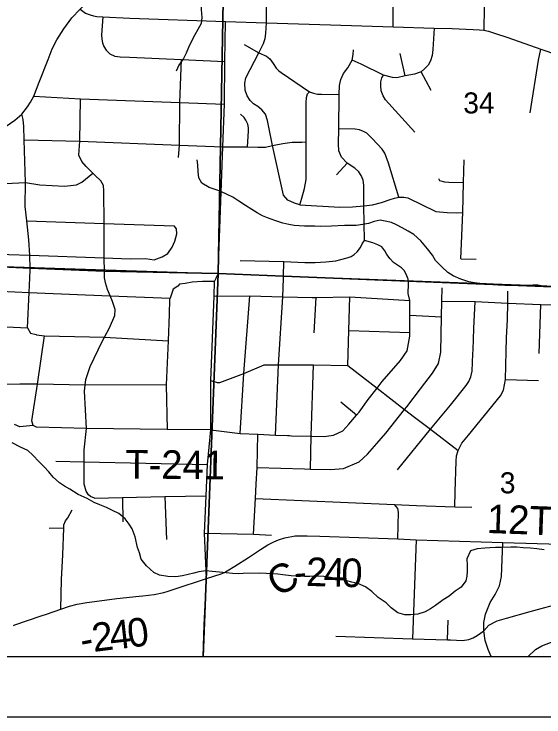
# Model space of a CAD drawing. Extents: x 0 to 34, y 0 to 22.
# Drawn here: x 5.78 to 6.833, y 14 to 15.396 of the extents above; entities that cross this region are included whole.
import ezdxf

# ---------------------------------------------------------------- set-up
doc = ezdxf.new("R2010")
doc.units = 0
for name, color, linetype in [('GM_X_Corporation', 7, 'Continuous'), ('GM_X_County_Road', 7, 'Continuous'), ('GM_X_County_Road_Text', 7, 'Continuous'), ('GM_X_Minor_River', 7, 'Continuous'), ('GM_X_Section_Text', 7, 'Continuous'), ('GM_X_Township_Road', 7, 'Continuous'), ('GM_X_Township_Road_Text', 7, 'Continuous'), ('SH_Data', 7, 'Continuous')]:
    doc.layers.add(name, color=color, linetype=linetype)

msp = doc.modelspace()

# ---------------------------------------------------------------- linework, layer by layer
at = {"layer": 'GM_X_Corporation'}
for points in [[(7.1023, 20.9204), (2.837, 20.9204), (2.837, 14.1204), (9.637, 14.1204), (9.637, 20.9204), (9.4036, 20.9204), (9.4022, 20.8667), (9.2273, 20.8723), (9.1354, 20.8749), (9.124, 20.8753), (8.9858, 20.878), (8.9676, 20.8785), (8.8663, 20.881), (8.6259, 20.8892), (8.5535, 20.8914), (8.5421, 20.8915), (8.4667, 20.8934), (8.0602, 20.9055), (7.9522, 20.9084), (7.1104, 20.9188)], [(5.1712, 15.9307), (6.2042, 15.8911), (6.1854, 14.88), (5.1298, 14.9148)], [(6.2042, 15.8911), (7.2356, 15.8559), (7.2089, 14.8416), (6.1854, 14.88)], [(5.1073, 14.1204), (6.1556, 14.1204), (6.1854, 14.88), (5.1298, 14.9148)], [(6.1556, 14.1204), (7.184, 14.1204), (7.2089, 14.8416), (6.1854, 14.88)]]:
    msp.add_lwpolyline(points, close=True, dxfattribs=at)
for points in [[(8.4248, 14.7958), (7.8005, 14.8186), (7.7106, 14.8199), (7.6921, 14.8213), (7.4889, 14.8294), (6.5635, 14.8658), (6.3152, 14.8755), (6.1855, 14.8807), (5.9592, 14.8856), (5.8117, 14.8915), (5.7258, 14.8953), (5.662, 14.8972), (5.3668, 14.9059), (5.2868, 14.911), (5.2181, 14.9126), (5.1335, 14.9126)], [(5.1335, 14.9126), (5.2181, 14.9126), (5.2868, 14.911), (5.3668, 14.9059), (5.662, 14.8972), (5.7258, 14.8953), (5.8117, 14.8915), (5.9592, 14.8856), (6.1855, 14.8807), (6.3152, 14.8755), (6.5635, 14.8658), (7.4889, 14.8294), (7.6921, 14.8213), (7.7106, 14.8199), (7.8005, 14.8186), (8.4248, 14.7958)], [(3.0474, 14.1204), (9.2101, 14.1204)]]:
    msp.add_lwpolyline(points, dxfattribs=at)
at = {"layer": 'GM_X_County_Road'}
for points in [[(5.6145, 15.1191), (5.6175, 15.1203), (5.6338, 15.126), (5.6814, 15.1424), (5.732, 15.1595), (5.7488, 15.1661), (5.7643, 15.1736), (5.7818, 15.1854), (5.7952, 15.1976), (5.8068, 15.212), (5.8129, 15.2215), (5.8193, 15.2329), (5.8302, 15.2613), (5.8476, 15.3063), (5.856, 15.3274), (5.865, 15.3452), (5.879, 15.367), (5.8949, 15.3886), (5.9111, 15.406), (5.9846, 15.4793), (6.0068, 15.5016), (6.0179, 15.5128)], [(5.9111, 15.406), (5.9217, 15.3983), (5.931, 15.3945), (5.9376, 15.3927), (5.9443, 15.3913), (5.9561, 15.3908), (6.0101, 15.3883), (6.2004, 15.3814), (6.2816, 15.3786), (6.4091, 15.3749), (6.5336, 15.3708), (6.6147, 15.3683), (6.6506, 15.3674), (6.6923, 15.3658), (6.7048, 15.3649), (6.7136, 15.3641), (6.7227, 15.3622), (6.7349, 15.3585), (6.761, 15.3495), (6.8267, 15.3266), (6.891, 15.3044)], [(6.2499, 14.3197), (6.2699, 14.3324), (6.2845, 14.3423), (6.2962, 14.3481), (6.3053, 14.3519), (6.3183, 14.3561), (6.3385, 14.3598), (6.3626, 14.3598), (6.3874, 14.359)], [(6.3874, 14.359), (6.5426, 14.3539), (6.5792, 14.3522), (6.7516, 14.3468), (6.979, 14.3397), (7.0782, 14.3359), (7.2017, 14.3322), (7.361, 14.3265), (7.4872, 14.3228), (7.6653, 14.3168), (7.7263, 14.3144), (7.7972, 14.3116), (7.9431, 14.3054), (8.0388, 14.3013), (8.2574, 14.2927), (8.4556, 14.2841), (8.5559, 14.2812), (8.5818, 14.2806), (8.7041, 14.2756), (8.8353, 14.2719), (8.9607, 14.2676), (9.0887, 14.2645), (9.2143, 14.2602)], [(6.0287, 14.2398), (6.0357, 14.2405), (6.0585, 14.2436), (6.0774, 14.2476), (6.0862, 14.2501), (6.0979, 14.2537), (6.1622, 14.275), (6.1916, 14.2845), (6.1981, 14.2871), (6.2038, 14.2902), (6.2186, 14.2995), (6.2457, 14.317), (6.2499, 14.3197)], [(5.8444, 14.2044), (5.8729, 14.2142), (5.8904, 14.2204), (5.9056, 14.2242), (5.9248, 14.2276), (5.9396, 14.2295)], [(5.9396, 14.2295), (5.9841, 14.2351), (6.0287, 14.2398)], [(5.7788, 14.1819), (5.7816, 14.1829), (5.8339, 14.2008), (5.8444, 14.2044)]]:
    msp.add_lwpolyline(points, dxfattribs=at)
at = {"layer": 'GM_X_Minor_River'}
for points in [[(6.1557, 15.4671), (6.1555, 15.4534), (6.153, 15.4428), (6.1509, 15.4302), (6.151, 15.4196), (6.1516, 15.4051), (6.1529, 15.3892), (6.1516, 15.3774), (6.1449, 15.3655), (6.139, 15.3552), (6.1338, 15.3449), (6.1268, 15.3296), (6.122, 15.3189), (6.1165, 15.3078), (6.1075, 15.2947), (6.102, 15.2829)], [(6.8381, 14.8544), (6.8206, 14.8575), (6.8111, 14.8578), (6.7997, 14.8572), (6.7755, 14.8569), (6.7648, 14.8571), (6.755, 14.857), (6.7424, 14.8579), (6.731, 14.8589), (6.7185, 14.8603), (6.7056, 14.8609), (6.695, 14.8622), (6.6839, 14.8643), (6.6679, 14.8698), (6.6527, 14.8764), (6.642, 14.8828), (6.63, 14.894), (6.6177, 14.9067), (6.6115, 14.9173), (6.6015, 14.9301), (6.5887, 14.9458), (6.5745, 14.9586), (6.5634, 14.9652), (6.5512, 14.9719), (6.5401, 14.9778), (6.5302, 14.9823), (6.5177, 14.9851), (6.5078, 14.9869), (6.4957, 14.984), (6.4847, 14.9805), (6.4734, 14.978), (6.4597, 14.9763), (6.4366, 14.976), (6.4108, 14.9749), (6.3896, 14.9746), (6.3778, 14.9748), (6.3672, 14.975), (6.3569, 14.9753), (6.3463, 14.9759), (6.3364, 14.9765), (6.3262, 14.9782), (6.3144, 14.9807), (6.2984, 14.9862), (6.2835, 14.9917), (6.274, 14.9958), (6.2629, 15.0017), (6.2526, 15.0084), (6.2399, 15.0158), (6.2265, 15.0247), (6.2147, 15.0329), (6.2036, 15.0377), (6.1906, 15.044), (6.1796, 15.0476), (6.1674, 15.052), (6.1532, 15.0602), (6.147, 15.0711), (6.1457, 15.0832), (6.1451, 15.0969), (6.1439, 15.1064)], [(6.3675, 14.279), (6.3569, 14.2792), (6.3455, 14.2798), (6.3307, 14.2807), (6.3144, 14.2824), (6.3041, 14.2838), (6.2927, 14.2844), (6.281, 14.2853), (6.2677, 14.2855), (6.2351, 14.2851), (6.2252, 14.2846), (6.2138, 14.2852), (6.2013, 14.2865), (6.188, 14.2875), (6.1735, 14.2892), (6.161, 14.2901), (6.147, 14.2884), (6.1372, 14.2856), (6.1258, 14.2828), (6.1145, 14.2803), (6.1012, 14.2786), (6.0857, 14.2788), (6.0693, 14.282), (6.0575, 14.2871), (6.0433, 14.3002), (6.0325, 14.3134), (6.0293, 14.3263), (6.0253, 14.3368), (6.0205, 14.3581), (6.015, 14.3736), (6.0088, 14.3833), (6.0007, 14.3939), (5.988, 14.4043), (5.9754, 14.4099), (5.9636, 14.4161), (5.9506, 14.4217), (5.9395, 14.4261), (5.925, 14.4342), (5.9071, 14.4423), (5.8906, 14.4527), (5.8799, 14.4583), (5.8703, 14.4654), (5.858, 14.4766), (5.8488, 14.4867), (5.8399, 14.4969), (5.8299, 14.507), (5.8172, 14.5201), (5.8073, 14.5291), (5.7931, 14.5361), (5.7763, 14.5446)], [(6.8334, 14.3319), (6.8186, 14.3339), (6.8061, 14.3353), (6.7916, 14.3362), (6.7795, 14.3372), (6.767, 14.3374), (6.748, 14.3367), (6.737, 14.3366), (6.7252, 14.336), (6.7154, 14.3355), (6.7006, 14.3338), (6.6874, 14.3302), (6.68, 14.3141), (6.6802, 14.3008), (6.6807, 14.2894), (6.6801, 14.2799), (6.678, 14.2704), (6.6683, 14.2581), (6.6566, 14.25), (6.6446, 14.2403), (6.6329, 14.2329), (6.6175, 14.2213), (6.6078, 14.2147), (6.5968, 14.2092), (6.5821, 14.2045), (6.5681, 14.2027), (6.5567, 14.203), (6.543, 14.207), (6.5292, 14.2166), (6.5192, 14.2268), (6.5039, 14.2376), (6.4912, 14.2495), (6.4782, 14.2585), (6.4629, 14.2651), (6.4511, 14.268), (6.4412, 14.2705), (6.4294, 14.273), (6.4161, 14.2755), (6.4051, 14.2776), (6.3956, 14.279), (6.3808, 14.2795), (6.3675, 14.279)]]:
    msp.add_lwpolyline(points, dxfattribs=at)
at = {"layer": 'GM_X_Township_Road'}
for p, q in [((6.5574, 15.2736), (6.5475, 15.3179)), ((6.6087, 15.2443), (6.5888, 15.2817)), ((6.4207, 15.0769), (6.4417, 15.0998)), ((6.6677, 14.9102), (6.6981, 14.9097)), ((6.63, 14.8258), (6.6305, 14.8525)), ((6.3762, 14.763), (6.3803, 14.8334)), ((6.5667, 14.798), (6.5668, 14.8276)), ((6.6294, 14.7951), (6.63, 14.8258)), ((6.8238, 14.722), (6.8272, 14.8197)), ((6.5667, 14.798), (6.6294, 14.7951)), ((6.4453, 14.7677), (6.5664, 14.7635)), ((5.8263, 14.6611), (5.8407, 14.7571)), ((6.7568, 14.6702), (6.8222, 14.6683)), ((6.4606, 14.5993), (6.4297, 14.6256)), ((6.0794, 14.4379), (6.0828, 14.3524)), ((6.6557, 14.4175), (6.6567, 14.4475)), ((5.9953, 14.4362), (5.9959, 14.3878)), ((5.8787, 14.3749), (5.85, 14.3743)), ((6.5792, 14.3522), (6.5717, 14.1552)), ((6.6416, 14.1534), (6.6427, 14.1925))]:
    msp.add_line(p, q, dxfattribs=at)
for points in [[(6.7251, 15.858), (6.722, 15.7474), (6.7201, 15.6445), (6.7187, 15.5989), (6.7172, 15.5257), (6.7156, 15.4542), (6.7149, 15.4305), (6.7145, 15.4107), (6.7136, 15.3641)], [(6.5336, 15.3708), (6.5331, 15.4317), (6.5348, 15.4894), (6.5359, 15.5583), (6.5368, 15.5992), (6.5385, 15.6082), (6.5429, 15.6177), (6.5505, 15.6258), (6.5606, 15.6314), (6.6203, 15.6474), (6.634, 15.6513), (6.6522, 15.6519)], [(6.2816, 15.3883), (6.2816, 15.4192), (6.2825, 15.4856)], [(5.9561, 15.3908), (5.9539, 15.3552), (5.9545, 15.3461), (5.9559, 15.3392), (5.9587, 15.3316), (5.9628, 15.3244), (5.9703, 15.3171), (5.9805, 15.3126), (5.9906, 15.311), (6.0097, 15.3105), (6.1129, 15.3061), (6.1987, 15.3022)], [(6.3478, 15.0175), (6.3375, 15.0205), (6.3243, 15.0269), (6.3153, 15.0368), (6.2938, 15.1351), (6.2834, 15.1849), (6.2794, 15.1973), (6.2727, 15.2063), (6.2643, 15.2127), (6.256, 15.218), (6.249, 15.2249), (6.2431, 15.234), (6.2393, 15.2449), (6.2383, 15.2591), (6.2403, 15.2693), (6.2665, 15.3191), (6.2759, 15.3381), (6.2792, 15.3478), (6.2804, 15.3577), (6.2816, 15.3786), (6.2816, 15.3883)], [(6.1817, 14.8718), (6.1839, 14.8764), (6.1857, 14.8801), (6.1948, 15.1327), (6.1984, 15.2175), (6.1987, 15.3022), (6.2004, 15.3814)], [(6.6147, 15.3683), (6.612, 15.3261), (6.6108, 15.3143), (6.6075, 15.3034), (6.6027, 15.295), (6.5954, 15.2875), (6.5888, 15.2817), (6.5755, 15.2772), (6.5574, 15.2736), (6.5406, 15.2693), (6.5318, 15.27), (6.514, 15.2751), (6.47, 15.2968), (6.4517, 15.3049)], [(6.237, 15.3357), (6.2665, 15.3191), (6.2816, 15.3125), (6.288, 15.3074), (6.2946, 15.298), (6.3012, 15.289), (6.306, 15.2835), (6.3109, 15.2805), (6.367, 15.2419), (6.3754, 15.2389), (6.3833, 15.2371), (6.3911, 15.2374), (6.4261, 15.2362)], [(6.2296, 14.9067), (6.3163, 14.9045), (6.3576, 14.9029), (6.3787, 14.9028), (6.3998, 14.9041), (6.4197, 14.906), (6.4297, 14.9088), (6.4419, 14.9119), (6.4497, 14.915), (6.4556, 14.9188), (6.4619, 14.9242), (6.4682, 14.9325), (6.4719, 14.9399), (6.4762, 14.9467), (6.4752, 15.0155), (6.4749, 15.0561), (6.4735, 15.0663), (6.4701, 15.0753), (6.4652, 15.0828), (6.457, 15.0901), (6.4417, 15.0998), (6.4308, 15.112), (6.4253, 15.1248), (6.4249, 15.1388), (6.4253, 15.168), (6.4261, 15.2362), (6.427, 15.2546), (6.4297, 15.2666), (6.4348, 15.2781), (6.4433, 15.2893), (6.4517, 15.3049), (6.4538, 15.3161), (6.4547, 15.3254)], [(6.806, 15.2003), (6.8223, 15.3046), (6.8267, 15.3266)], [(6.107, 15.1116), (6.1085, 15.1357), (6.1097, 15.2208), (6.1129, 15.3061)], [(6.5764, 15.1614), (6.5179, 15.2262), (6.5134, 15.2338), (6.5098, 15.2437), (6.5086, 15.2537), (6.5092, 15.2615), (6.511, 15.2697), (6.514, 15.2751)], [(5.8193, 15.2329), (5.9122, 15.2279), (6.1097, 15.2208), (6.1984, 15.2175)], [(6.3478, 15.0175), (6.3521, 15.0308), (6.3572, 15.0496), (6.3606, 15.0676), (6.3606, 15.1428), (6.3603, 15.2199), (6.3609, 15.2304), (6.3634, 15.2377), (6.367, 15.2419)], [(5.9602, 14.8696), (5.96, 14.8707), (5.9594, 14.8851), (5.9589, 14.9121), (5.9588, 14.9802), (5.9587, 15.045), (5.9576, 15.0556), (5.9523, 15.0648), (5.9403, 15.0765), (5.9367, 15.0801), (5.9233, 15.0933), (5.9147, 15.1032), (5.9087, 15.1157), (5.9106, 15.1436), (5.9122, 15.2279)], [(5.8117, 14.8868), (5.8119, 14.8909), (5.8116, 14.9173), (5.8094, 14.9481), (5.8052, 14.9854), (5.802, 15.0141), (5.8027, 15.062), (5.8002, 15.1465), (5.7993, 15.1731), (5.7984, 15.1867), (5.7952, 15.1976)], [(6.2441, 15.1323), (6.2462, 15.1634), (6.246, 15.1706), (6.2445, 15.1774), (6.2407, 15.1857), (6.237, 15.1907), (6.2298, 15.1972)], [(6.5445, 15.0323), (6.524, 15.0998), (6.5167, 15.1201), (6.5113, 15.1276), (6.492, 15.1487), (6.4808, 15.1596), (6.4745, 15.1632), (6.4667, 15.1662), (6.4579, 15.1677), (6.4253, 15.168)], [(5.8002, 15.1465), (5.9106, 15.1436), (6.1085, 15.1357), (6.1948, 15.1327), (6.2441, 15.1323), (6.2644, 15.1317), (6.2798, 15.1317), (6.2938, 15.1351), (6.2969, 15.136), (6.314, 15.139), (6.3324, 15.142), (6.3521, 15.1419), (6.3606, 15.1428)], [(6.6677, 14.9102), (6.6716, 15.0021), (6.6733, 15.0616), (6.6746, 15.1069)], [(5.7256, 14.8867), (5.726, 14.8947), (5.7271, 14.9203), (5.7265, 14.9344), (5.7224, 14.9476), (5.7171, 14.9575), (5.713, 14.9632), (5.7089, 14.9697), (5.7062, 14.9735), (5.7036, 14.9799), (5.6995, 14.9955), (5.7003, 15.0076), (5.7038, 15.0247), (5.7099, 15.0391), (5.7213, 15.0496), (5.7304, 15.0549), (5.7489, 15.059), (5.7761, 15.0601), (5.8027, 15.062), (5.8309, 15.0568), (5.8801, 15.0544), (5.9043, 15.057), (5.9149, 15.0622), (5.9367, 15.0801)], [(6.6232, 15.0697), (6.6258, 15.0654), (6.6352, 15.0633), (6.6442, 15.0624), (6.6733, 15.0616)], [(6.3478, 15.0175), (6.4277, 15.0128), (6.4525, 15.0135), (6.4752, 15.0155), (6.4926, 15.0171), (6.5103, 15.0217), (6.5273, 15.0277), (6.5363, 15.0305), (6.5445, 15.0323), (6.5544, 15.0326), (6.5626, 15.0311), (6.6185, 15.0043), (6.6404, 15.0021), (6.6583, 15.0013), (6.6716, 15.0021)], [(5.8052, 14.9854), (5.9588, 14.9802), (6.0979, 14.9755)], [(5.7271, 14.9203), (5.8116, 14.9173), (5.9589, 14.9121), (6.0104, 14.9102), (6.041, 14.9105), (6.0587, 14.9082), (6.0743, 14.9138), (6.0853, 14.921), (6.0944, 14.9331), (6.0997, 14.9452), (6.1036, 14.9596), (6.1025, 14.9698), (6.0979, 14.9755)], [(6.5636, 14.8602), (6.5637, 14.8652), (6.5633, 14.8699), (6.5607, 14.8765), (6.5556, 14.8862), (6.5501, 14.8919), (6.5439, 14.8962), (6.5339, 14.9025), (6.5273, 14.9099), (6.5208, 14.9184), (6.517, 14.9259), (6.5107, 14.9339), (6.5027, 14.9379), (6.4933, 14.9419), (6.4762, 14.9467)], [(6.3153, 14.8709), (6.3154, 14.875), (6.3163, 14.9045)], [(5.8065, 14.7728), (5.8097, 14.8433), (5.8117, 14.8868)], [(5.9193, 14.5304), (5.9242, 14.5733), (5.9198, 14.6471), (5.9213, 14.659), (5.9229, 14.6706), (5.9309, 14.6959), (5.9549, 14.7459), (5.9596, 14.7543), (5.9698, 14.7728), (5.9804, 14.7977), (5.9809, 14.8095), (5.9756, 14.8254), (5.971, 14.8367), (5.9659, 14.849), (5.9614, 14.8623), (5.9602, 14.8696)], [(6.1555, 14.1204), (6.1575, 14.1834), (6.1622, 14.275), (6.1587, 14.3654), (6.1619, 14.4396), (6.1644, 14.5018), (6.171, 14.5704), (6.1709, 14.6682), (6.1774, 14.8357), (6.1786, 14.8653), (6.1817, 14.8718)], [(6.2997, 14.56), (6.3054, 14.6997), (6.3143, 14.8349), (6.3153, 14.8709)], [(6.1786, 14.8653), (6.1542, 14.865), (6.1342, 14.8639), (6.1198, 14.8613), (6.1085, 14.8595), (6.1054, 14.8561), (6.0963, 14.85), (6.0929, 14.8402), (6.09, 14.8318), (6.0891, 14.8292), (6.0882, 14.8), (6.086, 14.7473), (6.0824, 14.6595), (6.0841, 14.5712)], [(6.5668, 14.8276), (6.5633, 14.8411), (6.5636, 14.8602)], [(5.7238, 14.8469), (5.8097, 14.8433), (5.9217, 14.8387)], [(6.758, 14.7263), (6.7586, 14.7534), (6.7604, 14.7893), (6.761, 14.8218), (6.7614, 14.8458)], [(5.9217, 14.8387), (5.971, 14.8367), (6.09, 14.8318)], [(6.1774, 14.8357), (6.2487, 14.8369), (6.3143, 14.8349), (6.3721, 14.8336)], [(6.2295, 14.5633), (6.2364, 14.6821), (6.2487, 14.8369)], [(6.3721, 14.8336), (6.3803, 14.8334), (6.447, 14.8349), (6.5668, 14.8276)], [(6.4431, 14.6979), (6.4453, 14.7677), (6.447, 14.8349)], [(6.63, 14.8258), (6.6964, 14.8252), (6.761, 14.8218), (6.8272, 14.8197), (6.888, 14.8178), (6.9799, 14.815), (7.06, 14.8126)], [(6.6922, 14.7291), (6.6938, 14.7718), (6.6964, 14.8252)], [(6.2629, 14.4954), (6.3574, 14.4929), (6.3688, 14.4926), (6.4088, 14.4916), (6.4345, 14.4939), (6.4656, 14.5071), (6.4826, 14.5218), (6.5012, 14.543), (6.519, 14.5638), (6.556, 14.611), (6.5604, 14.6164), (6.588, 14.6516), (6.6116, 14.6831), (6.6233, 14.702), (6.6279, 14.7244), (6.6294, 14.7951)], [(6.3313, 14.5588), (6.3707, 14.5579), (6.372, 14.5579), (6.3962, 14.5573), (6.4147, 14.5599), (6.4336, 14.5682), (6.445, 14.5814), (6.4606, 14.5993), (6.4658, 14.6053), (6.484, 14.631), (6.5013, 14.6532), (6.5117, 14.6666), (6.5477, 14.7082), (6.561, 14.7272), (6.5664, 14.7564), (6.5664, 14.7635), (6.5667, 14.798)], [(5.6506, 14.7825), (5.6915, 14.7768), (5.7206, 14.7762), (5.7649, 14.7753), (5.8065, 14.7728), (5.8124, 14.7623), (5.8238, 14.7595), (5.8248, 14.7594)], [(5.8248, 14.7594), (5.8407, 14.7571), (5.9596, 14.7543), (6.086, 14.7473)], [(6.5417, 14.4907), (6.6076, 14.5718), (6.6475, 14.6196), (6.6786, 14.6582), (6.6839, 14.6662), (6.6879, 14.676), (6.6903, 14.6869), (6.6919, 14.7215), (6.6922, 14.7291)], [(6.6567, 14.4475), (6.6587, 14.5085), (6.6592, 14.5186), (6.6624, 14.5295), (6.6701, 14.5438), (6.6831, 14.5595), (6.7467, 14.6377), (6.7525, 14.6491), (6.7568, 14.6702), (6.758, 14.7263)], [(6.1709, 14.6682), (6.1834, 14.6643), (6.1891, 14.6645), (6.2364, 14.6821), (6.2773, 14.6993), (6.3054, 14.6997), (6.3748, 14.6993), (6.4431, 14.6979), (6.5013, 14.6532), (6.556, 14.611), (6.5759, 14.5959)], [(6.3688, 14.4926), (6.3707, 14.5579), (6.3748, 14.6993)], [(6.171, 14.5704), (6.0841, 14.5712), (5.9242, 14.5733), (5.8248, 14.5759), (5.8177, 14.5788), (5.8156, 14.5883), (5.8263, 14.6611), (5.7917, 14.6612), (5.7392, 14.6603), (5.7126, 14.6586)], [(6.0824, 14.6595), (5.9213, 14.659), (5.8263, 14.6611)], [(6.5759, 14.5959), (6.6076, 14.5718), (6.6624, 14.5295)], [(5.8177, 14.5788), (5.7917, 14.5764), (5.7811, 14.5813)], [(6.171, 14.5704), (6.2295, 14.5633), (6.2644, 14.5617), (6.2997, 14.56), (6.3232, 14.5589), (6.3273, 14.5589), (6.3313, 14.5588)], [(6.2612, 14.4626), (6.2629, 14.4954), (6.2644, 14.5617)], [(5.9401, 14.435), (5.9318, 14.4381), (5.9277, 14.4412), (5.9236, 14.4484), (5.9191, 14.4624), (5.9192, 14.5069), (5.9192, 14.5094), (5.9193, 14.5304)], [(5.8633, 14.5081), (5.9192, 14.5069), (6.1644, 14.5018)], [(6.2559, 14.3633), (6.2597, 14.434), (6.2612, 14.4626)], [(5.9401, 14.435), (5.9953, 14.4362), (6.0794, 14.4379), (6.1619, 14.4396)], [(6.2597, 14.434), (6.5363, 14.4221), (6.5795, 14.4204)], [(5.8729, 14.2142), (5.8745, 14.273), (5.8766, 14.3223), (5.8787, 14.3749), (5.8791, 14.3814), (5.8825, 14.3898), (5.8867, 14.3954), (5.8954, 14.4113)], [(6.5426, 14.3539), (6.544, 14.4069), (6.5425, 14.4143), (6.5363, 14.4221)], [(6.5795, 14.4204), (6.6557, 14.4175), (6.6898, 14.4167)], [(6.1587, 14.3654), (6.2559, 14.3633), (6.2917, 14.3614)], [(6.7284, 14.1204), (6.7219, 14.1344), (6.7164, 14.1521), (6.7134, 14.1711), (6.7135, 14.1874), (6.7169, 14.204), (6.7262, 14.2275), (6.7362, 14.2435), (6.7446, 14.2607), (6.7484, 14.2792), (6.7516, 14.3468)], [(6.6475, 14.1532), (6.6711, 14.1523), (6.6836, 14.1539), (6.6925, 14.1574), (6.7005, 14.1619), (6.7134, 14.1711), (6.7238, 14.1821), (6.7403, 14.191), (6.7585, 14.1963), (6.8056, 14.2094), (6.8742, 14.2278), (6.9286, 14.243), (6.9652, 14.2529), (6.9732, 14.2575)], [(6.4193, 14.1606), (6.5717, 14.1552), (6.6416, 14.1534), (6.6475, 14.1532)], [(6.8018, 14.1204), (6.8165, 14.1339), (6.829, 14.1411), (6.8459, 14.148), (6.864, 14.1508), (6.8853, 14.1508)]]:
    msp.add_lwpolyline(points, dxfattribs=at)
at = {"layer": 'SH_Data'}
msp.add_line((2.7349, 14.0001), (9.7349, 14.0001), dxfattribs=at)

# ---------------------------------------------------------------- texts
at = {"layer": 'GM_X_County_Road_Text'}
for s, height, rotation, p in [('12TH', 0.05682, 357.9567, (6.7189, 14.3656)), ('2', 0.0568, 358.5844, (6.3598, 14.2604)), ('4', 0.0568, 358.3918, (6.3947, 14.2596)), ('0', 0.0568, 358.3606, (6.4297, 14.2586)), ('C', 0.0568, 30.7141, (6.3044, 14.2372)), ('-', 0.0568, 3.7731, (6.3379, 14.2589)), ('2', 0.0568, 7.1792, (5.9382, 14.1291)), ('4', 0.0568, 6.2833, (5.9727, 14.1334)), ('0', 0.0568, 7.5813, (6.0089, 14.1374)), ('-', 0.0568, 10.9793, (5.9163, 14.1248))]:
    msp.add_text(s, height=height, rotation=rotation, dxfattribs=at).set_placement(p)
at = {"layer": 'GM_X_Section_Text'}
for s, height, p in [('34', 0.04186, (6.6728, 15.1988)), ('3', 0.0419, (6.7453, 14.4442))]:
    msp.add_text(s, height=height, rotation=0, dxfattribs=at).set_placement(p)
at = {"layer": 'GM_X_Township_Road_Text'}
msp.add_text('T-241', height=0.05682, rotation=359.4386, dxfattribs=at).set_placement((6.0006, 14.4739))

doc.saveas('drawing.dxf')
